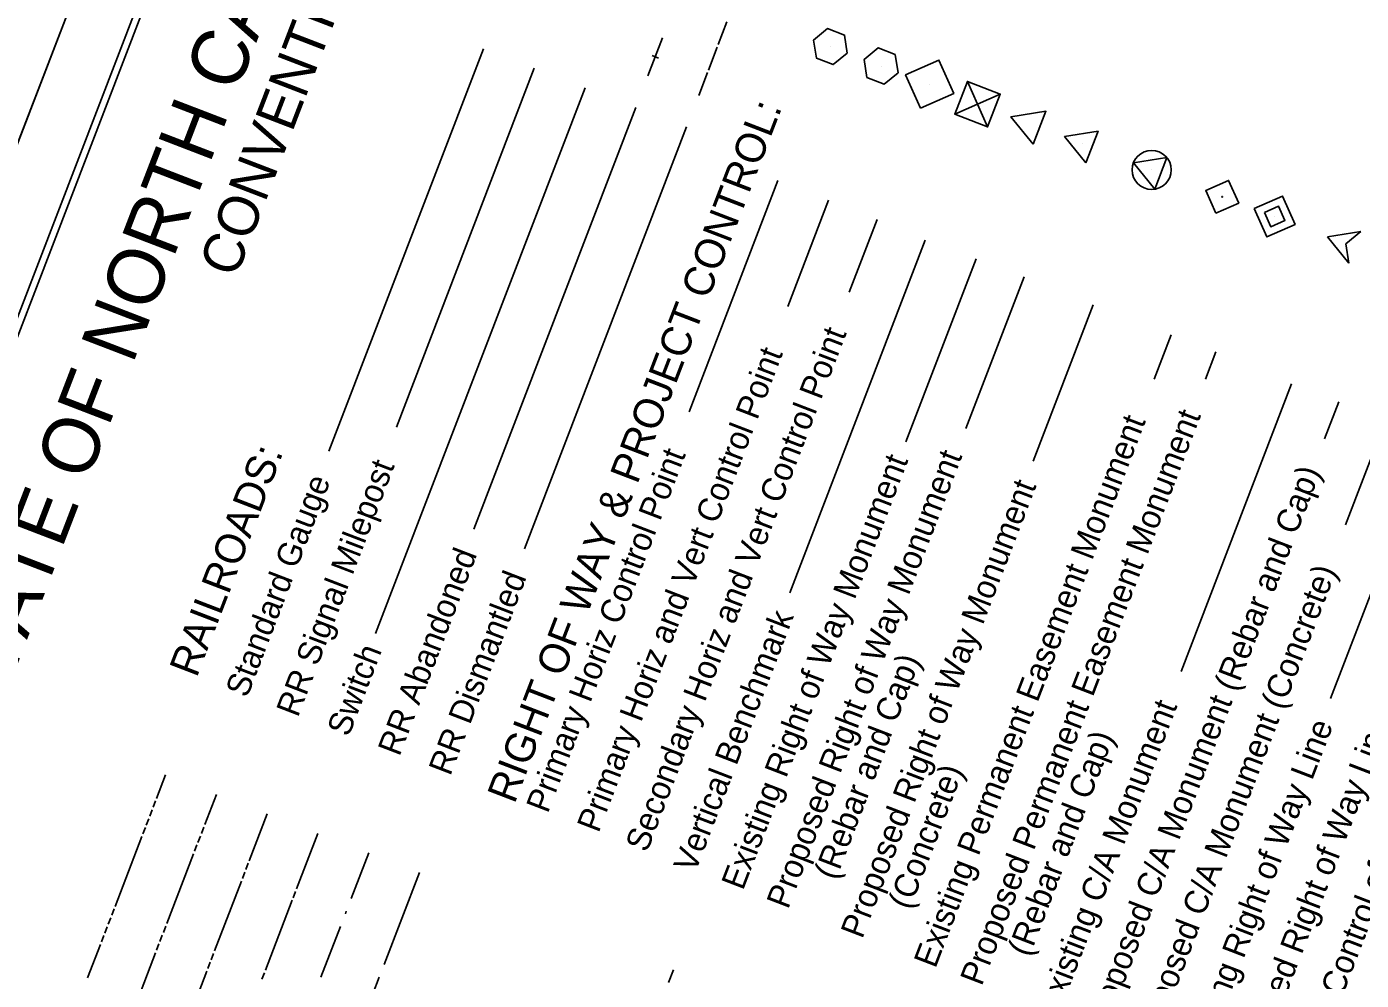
# Model space of a CAD drawing. Extents: x 1015221 to 1064345, y 619216 to 647967.
# Drawn here: x 1044921 to 1048770, y 627789 to 630539 of the extents above; entities that cross this region are included whole.
import ezdxf

# ---------------------------------------------------------------- set-up
doc = ezdxf.new("R2010")
doc.units = 0
for name, color, linetype in [('Default', 7, 'Continuous'), ('Sheet Cutting Line CELL', 7, 'Continuous'), ('Sheet Plot Border Inside CELL', 7, 'Continuous'), ('Sheet Plot Border Outside CELL', 7, 'Continuous'), ('Sheet Symbology CELL', 7, 'Continuous')]:
    doc.layers.add(name, color=color, linetype=linetype)

msp = doc.modelspace()

# ---------------------------------------------------------------- linework, layer by layer
at = {"layer": 'Default'}
for p, q in [((1046915.3, 630487.6), (1046940.6, 630553.5)), ((1046712.6, 630397.4), (1046754.8, 630507.2)), ((1046238.2, 630475.4), (1045792.5, 629315.2)), ((1046724.5, 630455.8), (1046742.8, 630448.8)), ((1046887.2, 630414.3), (1046912.5, 630480.2)), ((1047239, 630482), (1047239, 630482)), ((1046384.7, 630419.2), (1045987.2, 629384.4)), ((1046859, 630341.1), (1046884.4, 630407)), ((1047385.2, 630425.7), (1047385.2, 630425.7)), ((1047525.3, 630373), (1047525.3, 630373)), ((1046531.2, 630362.9), (1045926.4, 628788.8)), ((1046677.7, 630306.6), (1046210.1, 629089.6)), ((1047663.1, 630315.9), (1047663.1, 630315.9)), ((1046824.2, 630250.3), (1046356.6, 629033.3)), ((1046824.2, 630250.3), (1046356.6, 629033.3)), ((1047967.3, 630202.1), (1047967.3, 630202.1)), ((1048165.5, 630126.1), (1048165.5, 630126.1)), ((1047087.3, 630095.3), (1046831.2, 629428.6)), ((1047233.8, 630039.1), (1047115.9, 629732)), ((1048369.1, 630048.5), (1048369.1, 630048.5)), ((1048520.5, 629991.9), (1048520.5, 629991.9)), ((1047373.6, 629982.7), (1047293.2, 629773.6)), ((1048672.6, 629933.3), (1048769.3, 629948.7)), ((1048769.3, 629948.7), (1048725.4, 629913)), ((1047512.4, 629923.6), (1047121.7, 628906.7)), ((1048734.2, 629857.1), (1048672.6, 629933.3)), ((1048725.4, 629913), (1048734.2, 629857.1)), ((1047659.7, 629869.7), (1047456.9, 629341.9)), ((1047797.5, 629817.5), (1047629.4, 629380)), ((1047996.8, 629736.7), (1047823.8, 629286.4)), ((1048221.8, 629650.9), (1048172.5, 629522.4)), ((1048350.9, 629601.3), (1048320.5, 629522.2)), ((1048569.4, 629509.1), (1048250.8, 628679.7)), ((1048705.4, 629457.6), (1048664.5, 629350.9)), ((1048841, 629405.5), (1048724.5, 629102.4)), ((1048970, 629352.3), (1048681.5, 628601.4)), ((1045295.1, 628313.5), (1045321.3, 628381.6)), ((1045285.3, 628287.9), (1045292.3, 628306.2)), ((1045434.3, 628238.1), (1045467.8, 628325.3)), ((1045265.6, 628236.6), (1045272.6, 628254.9)), ((1045275.4, 628262.2), (1045282.5, 628280.5)), ((1045562.3, 628133.9), (1045614.3, 628269.1)), ((1045255.7, 628211), (1045262.8, 628229.3)), ((1045424.4, 628212.5), (1045431.4, 628230.8)), ((1045699.2, 628052.7), (1045760.7, 628212.8)), ((1045175.5, 628002.2), (1045252.9, 628203.6)), ((1045404.7, 628161.2), (1045411.7, 628179.5)), ((1045414.6, 628186.8), (1045421.6, 628205.1)), ((1045324.5, 627952.4), (1045401.9, 628153.9)), ((1045856.6, 628024.7), (1045907.2, 628156.5)), ((1045542.6, 628082.7), (1045549.7, 628101)), ((1045552.5, 628108.3), (1045559.5, 628126.6)), ((1045951.7, 627834.7), (1046053.7, 628100.2)), ((1045462.4, 627873.9), (1045539.8, 628075.3)), ((1045609.2, 627818.3), (1045686.6, 628019.7)), ((1045689.4, 628027), (1045696.4, 628045.3)), ((1045165.7, 627976.6), (1045172.7, 627994.9)), ((1045839.7, 627980.7), (1045842.5, 627988)), ((1045146, 627925.3), (1045153, 627943.6)), ((1045155.8, 627951), (1045162.9, 627969.3)), ((1045314.7, 627926.8), (1045321.7, 627945.1)), ((1045769.3, 627797.6), (1045825.6, 627944.1)), ((1045136.1, 627899.7), (1045143.2, 627918)), ((1045304.8, 627901.2), (1045311.8, 627919.5)), ((1045096.2, 627795.7), (1045133.3, 627892.4)), ((1045242.7, 627739.4), (1045292.1, 627868.2)), ((1045295, 627875.5), (1045302, 627893.9)), ((1045452.6, 627848.3), (1045459.6, 627866.6)), ((1045442.7, 627822.7), (1045449.8, 627841)), ((1045389.1, 627683.1), (1045439.9, 627815.3)), ((1045599.3, 627792.6), (1045606.4, 627811)), ((1045828.6, 627514.3), (1045937.6, 627798.1)), ((1046772.3, 627782.9), (1046786.1, 627818.8))]:
    msp.add_line(p, q, dxfattribs=at)
for points in [[(1047287.7, 630463.3), (1047247.3, 630430.1), (1047198.6, 630448.8), (1047190.3, 630500.7), (1047230.7, 630533.9), (1047279.9, 630515), (1047287.7, 630463.3)], [(1047633.9, 630381.5), (1047692.3, 630250.1), (1047663.1, 630315.8), (1047728.8, 630345), (1047597.4, 630286.6)], [(1047663.1, 630315.8), (1047633.9, 630381.5), (1047597.4, 630286.6), (1047663.1, 630315.8)], [(1047663.1, 630315.8), (1047692.3, 630250.1), (1047728.8, 630345), (1047663.1, 630315.8)], [(1047824.2, 630200.3), (1047759.8, 630279.6), (1047860.7, 630295.4), (1047824.2, 630200.3)]]:
    msp.add_lwpolyline(points, dxfattribs=at)
for points in [[(1047344.1, 630392.5), (1047336.6, 630444.7), (1047376.7, 630478.5), (1047425.7, 630459), (1047434.2, 630406.4), (1047394, 630373.4)], [(1047498.6, 630304.2), (1047455.9, 630400.1), (1047552, 630442.8), (1047594.6, 630346.9)], [(1047597.4, 630286.6), (1047633.9, 630381.5), (1047728.8, 630345), (1047692.3, 630250.1)], [(1047976, 630146.2), (1047914.5, 630222.4), (1048011.2, 630237.8)], [(1048174.3, 630070.2), (1048112.8, 630146.4), (1048209.5, 630161.8)], [(1048350.8, 630001), (1048321.5, 630066.8), (1048387.4, 630096.1), (1048416.7, 630030.3)], [(1048461.6, 630014.5), (1048543.2, 630050.8), (1048579.5, 629969.2), (1048497.9, 629932.9)], [(1048491, 630003.2), (1048531.9, 630021.4), (1048550, 629980.5), (1048509.2, 629962.4)]]:
    msp.add_lwpolyline(points, close=True, dxfattribs=at)
for centre, radius in [((1048165.5, 630126.1), 56.5), ((1048369.1, 630048.5), 0.991)]:
    msp.add_circle(centre, radius, dxfattribs=at)
at = {"layer": 'Sheet Cutting Line CELL'}
msp.add_line((1047645.6, 637365.6), (1042813.9, 624789.8), dxfattribs=at)
at = {"layer": 'Sheet Plot Border Inside CELL'}
msp.add_lwpolyline([(1050898.2, 621795.3), (1055679.6, 634240.3), (1047800.3, 637267.6), (1043018.9, 624822.5)], close=True, dxfattribs=at)
at = {"layer": 'Sheet Plot Border Outside CELL'}
msp.add_lwpolyline([(1051028.5, 621633.8), (1055860.2, 634209.5), (1047645.6, 637365.6), (1042813.9, 624789.8)], close=True, dxfattribs=at)
at = {"layer": 'Sheet Symbology CELL'}
msp.add_lwpolyline([(1047783.5, 637166.9), (1043479.8, 625965.2), (1051313.4, 622955.5), (1055617.1, 634157.2)], close=True, dxfattribs=at)

# ---------------------------------------------------------------- texts
at = {"layer": 'Default'}
for s, height, p in [('STATE OF NORTH CAROLINA, DIVISION OF HIGHWAYS', 163.31, (1044821.1, 628509.7)), ('CONVENTIONAL  PLAN SHEET SYMBOLS', 116.65, (1045524.1, 629811.2)), ('RIGHT OF WAY & PROJECT CONTROL:', 86.308, (1046327.5, 628295.3)), ('Secondary Horiz and Vert Control Point', 68.654, (1046709.8, 628155.3)), ('Primary Horiz and Vert Control Point', 68.654, (1046570, 628211.7)), ('Existing Permanent Easement Monument', 68.654, (1047541.6, 627821)), ('Proposed Permanent Easement Monument', 68.654, (1047675.2, 627770)), ('RAILROADS:', 86.31, (1045410.6, 628659.4)), ('RR Signal Milepost', 68.654, (1045702.6, 628544.9)), ('Primary Horiz Control Point', 68.654, (1046423.5, 628268)), ('Existing Right of Way Monument', 68.654, (1046986.5, 628045.9)), ('Proposed Right of Way Monument', 68.654, (1047116.7, 627991.5)), ('Proposed C/A Monument (Rebar and Cap)', 68.654, (1048029.8, 627632.2)), ('Standard Gauge', 68.654, (1045556.2, 628601.2)), ('Proposed Right of Way Monument', 68.654, (1047330.6, 627906.1)), ('RR Abandoned', 68.654, (1045995.6, 628432.3)), ('RR Dismantled', 68.654, (1046142.1, 628376)), ('Proposed C/A Monument (Concrete)', 68.654, (1048165.3, 627580.1)), ('Vertical Benchmark', 68.654, (1046848.6, 628096.2)), ('Switch', 68.65, (1045849.1, 628488.6)), ('     (Rebar and Cap)', 68.654, (1047208.3, 627956.3)), ('Existing C/A Monument', 68.654, (1047896.3, 627685.3)), ('Existing Control of Access Line', 68.654, (1048590.6, 627415.6)), ('Proposed Control of Access Line', 68.654, (1048735.4, 627355.4)), ('Existing Right of Way Line', 68.654, (1048306.1, 627524.9)), ('Proposed Right of Way Line', 68.654, (1048448, 627470.4)), ('     (Rebar and Cap)', 68.654, (1047766.8, 627734.8)), ('     (Concrete)', 68.654, (1047422.2, 627870.9))]:
    msp.add_text(s, height=height, rotation=68.983, dxfattribs=at).set_placement(p)

doc.saveas('drawing.dxf')
